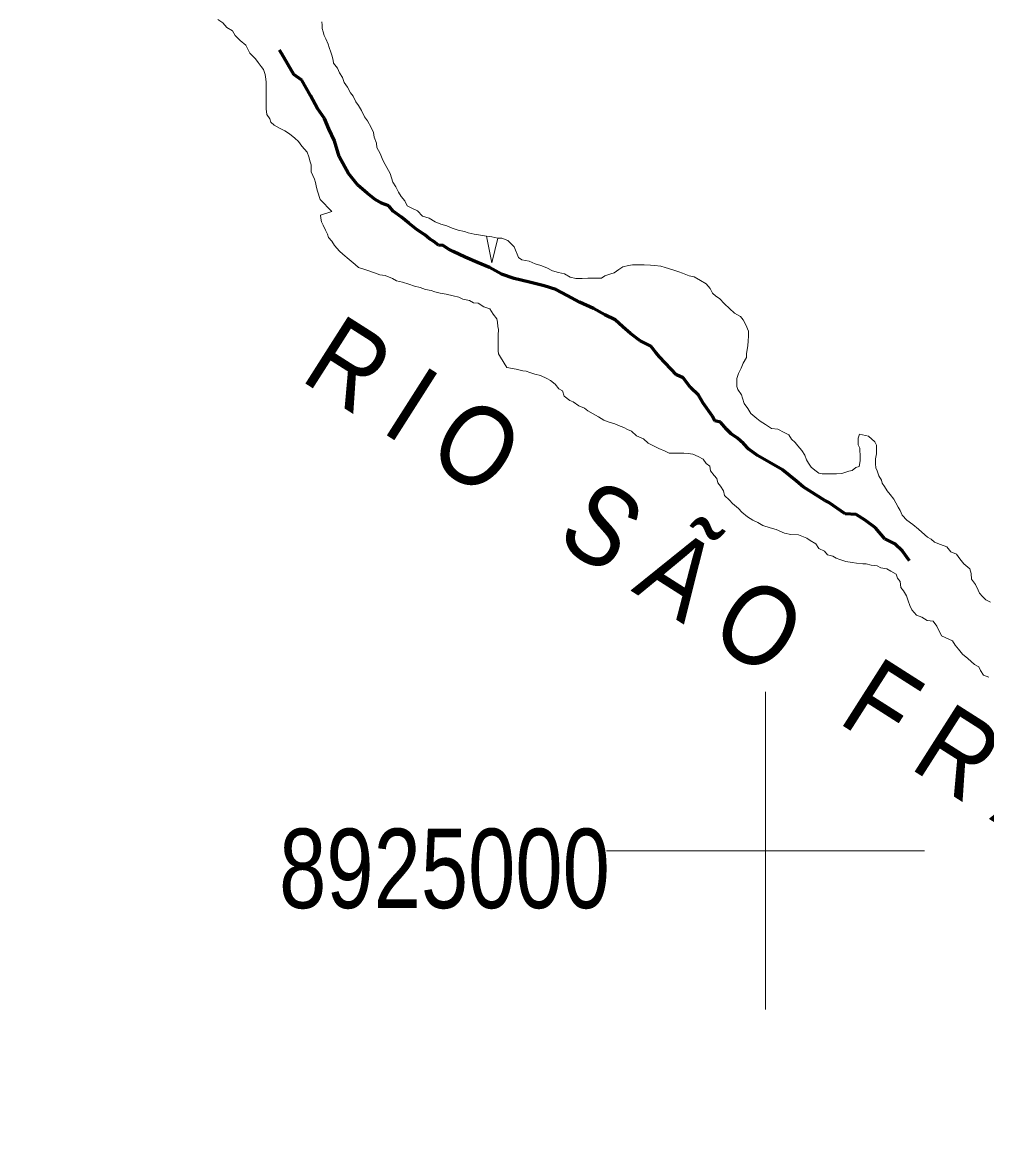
# Model space of a CAD drawing. Extents: x -1643653 to 4543381, y 1624270 to 13878484.
# Drawn here: x 645322 to 651392, y 8923156 to 8930215 of the extents above; entities that cross this region are included whole.
import ezdxf
from ezdxf.enums import TextEntityAlignment as Align

# ---------------------------------------------------------------- set-up
doc = ezdxf.new("R2010")
doc.units = 0
doc.header["$LTSCALE"] = 200
doc.linetypes.add('LONG_DASH_SHORT_DASH', pattern=[9.9, 6, -1.2, 1.5, -1.2])
for name, color, linetype, lineweight in [('2', 7, 'Continuous', 13), ('23', 7, 'Continuous', 13), ('25', 7, 'Continuous', 13), ('60', 7, 'Continuous', 13), ('7', 7, 'LONG_DASH_SHORT_DASH', 60)]:
    doc.layers.add(name, color=color, linetype=linetype, lineweight=lineweight)
for name, color, linetype in [('42', 7, 'Continuous'), ('47', 7, 'Continuous'), ('49', 7, 'Continuous')]:
    doc.layers.add(name, color=color, linetype=linetype)

msp = doc.modelspace()

# ---------------------------------------------------------------- linework, layer by layer
at = {"layer": '2'}
for p, q in [((650000, 8924000), (650000, 8926000)), ((649000, 8925000), (651000, 8925000))]:
    msp.add_line(p, q, dxfattribs=at)
at = {"layer": '23'}
for points in [[(648771.1, 8928610.7), (648733.8, 8928630.9), (648696.3, 8928641.2), (648658.9, 8928651.4), (648624, 8928669.2), (648586.6, 8928684.5), (648549.2, 8928694.7), (648511.8, 8928712.5), (648466.8, 8928720.3), (648444.5, 8928735.5), (648417.4, 8928800.8), (648377.7, 8928841.1), (648340.3, 8928856.3), (648315.3, 8928856.5), (648277.9, 8928864.3), (648242.9, 8928869.5), (648205.4, 8928874.8), (648165.5, 8928882.5), (648128, 8928890.3), (648105.5, 8928897.9), (648065.6, 8928905.7), (648028.2, 8928918.5), (647993.3, 8928933.7), (647955.8, 8928944), (647920.9, 8928959.3), (647883.6, 8928982), (647841.2, 8928994.8), (647808.9, 8929027.6), (647779, 8929042.8), (647744.1, 8929060.6), (647729.3, 8929090.7), (647707, 8929118.4), (647689.7, 8929146.1), (647672.5, 8929178.7), (647655.2, 8929208.9), (647638.1, 8929264.1), (647606, 8929319.3), (647591.2, 8929347), (647574, 8929389.7), (647554.3, 8929427.3), (647552, 8929454.9), (647537.3, 8929492.5), (647532.5, 8929522.6), (647517.8, 8929552.8), (647495.6, 8929595.5), (647475.8, 8929620.6), (647456.1, 8929660.8), (647438.8, 8929691), (647421.4, 8929713.6), (647404.2, 8929751.3), (647386.9, 8929771.4), (647369.6, 8929806.6), (647347.3, 8929836.8), (647337.6, 8929866.9), (647317.8, 8929897.1), (647305.5, 8929927.2), (647280.7, 8929957.4), (647278.4, 8929977.4), (647271.1, 8930007.5), (647263.8, 8930027.6), (647254, 8930057.7), (647246.6, 8930077.8), (647231.9, 8930110.4), (647222, 8930133), (647214.7, 8930155.6), (647209.9, 8930175.7), (647210, 8930198.2), (647207.7, 8930218.2)], [(648771.1, 8928610.7), (648733.8, 8928630.9), (648696.3, 8928641.2), (648658.9, 8928651.4), (648624, 8928669.2), (648586.6, 8928684.5), (648549.2, 8928694.7), (648511.8, 8928712.5), (648466.8, 8928720.3), (648444.5, 8928735.5), (648417.4, 8928800.8), (648377.7, 8928841.1), (648340.3, 8928856.3), (648315.3, 8928856.5), (648277.9, 8928864.3), (648242.9, 8928869.5), (648205.4, 8928874.8), (648165.5, 8928882.5), (648128, 8928890.3), (648105.5, 8928897.9), (648065.6, 8928905.7), (648028.2, 8928918.5), (647993.3, 8928933.7), (647955.8, 8928944), (647920.9, 8928959.3), (647883.6, 8928982), (647841.2, 8928994.8), (647808.9, 8929027.6), (647779, 8929042.8), (647744.1, 8929060.6), (647729.3, 8929090.7), (647707, 8929118.4), (647689.7, 8929146.1), (647672.5, 8929178.7), (647655.2, 8929208.9), (647638.1, 8929264.1), (647606, 8929319.3), (647591.2, 8929347), (647574, 8929389.7), (647554.3, 8929427.3), (647552, 8929454.9), (647537.3, 8929492.5), (647532.5, 8929522.6), (647517.8, 8929552.8), (647495.6, 8929595.5), (647475.8, 8929620.6), (647456.1, 8929660.8), (647438.8, 8929691), (647421.4, 8929713.6), (647404.2, 8929751.3), (647386.9, 8929771.4), (647369.6, 8929806.6), (647347.3, 8929836.8), (647337.6, 8929866.9), (647317.8, 8929897.1), (647305.5, 8929927.2), (647280.7, 8929957.4), (647278.4, 8929977.4), (647271.1, 8930007.5), (647263.8, 8930027.6), (647254, 8930057.7), (647246.6, 8930077.8), (647231.9, 8930110.4), (647222, 8930133), (647214.7, 8930155.6), (647209.9, 8930175.7), (647210, 8930198.2), (647207.7, 8930218.2)], [(650693.1, 8927436.3), (650693.3, 8927466.3), (650698.5, 8927498.8), (650698.7, 8927521.4), (650699, 8927553.9), (650689.1, 8927574), (650649.4, 8927609.3), (650591.9, 8927622.2), (650584.2, 8927597.2), (650584.1, 8927577.2), (650583.9, 8927554.7), (650593.8, 8927534.6), (650593.6, 8927514.6), (650596, 8927494.5), (650595.8, 8927474.5), (650595.7, 8927454.5), (650590.4, 8927419.4), (650567.8, 8927412.1), (650545.2, 8927394.7), (650525.1, 8927389.8), (650505.1, 8927382.5), (650480, 8927375.1), (650447.5, 8927372.8), (650425, 8927373), (650405, 8927373.1), (650380, 8927373.3), (650357.4, 8927373.4), (650335, 8927376.1), (650310.1, 8927396.3), (650287.7, 8927413.9), (650270.4, 8927439.1), (650258.1, 8927461.7), (650248.3, 8927489.3), (650228.5, 8927519.5), (650203.7, 8927549.7), (650186.3, 8927569.8), (650164, 8927590), (650146.7, 8927617.7), (650116.8, 8927632.9), (650076.9, 8927653.2), (650037, 8927658.4), (649999.6, 8927683.7), (649967.3, 8927704), (649944.9, 8927721.6), (649907.6, 8927751.9), (649887.9, 8927784.6), (649865.6, 8927814.8), (649855.8, 8927849.9), (649848.5, 8927870), (649826.2, 8927902.7), (649818.9, 8927922.8), (649819, 8927942.8), (649819.3, 8927972.8), (649829.5, 8928005.3), (649847.3, 8928037.7), (649860, 8928070.2), (649880.3, 8928105.1), (649880.5, 8928127.6), (649885.7, 8928155.1), (649888.3, 8928177.7), (649891.1, 8928210.2), (649893.8, 8928240.2), (649894.1, 8928270.2), (649876.8, 8928310.4), (649859.6, 8928343.1), (649842.2, 8928363.2), (649804.9, 8928383.5), (649772.6, 8928413.8), (649742.8, 8928444), (649710.5, 8928476.8), (649688.2, 8928491.9), (649665.8, 8928509.6), (649651, 8928539.7), (649626.2, 8928569.9), (649591.3, 8928590.2), (649551.5, 8928613), (649519, 8928618.2), (649476.7, 8928636), (649454.2, 8928643.7), (649416.8, 8928656.4), (649369.4, 8928671.8), (649341.9, 8928679.5), (649301.9, 8928684.7), (649277, 8928687.4), (649236.9, 8928687.7), (649201.9, 8928687.9), (649161.9, 8928688.2), (649136.9, 8928683.3), (649101.8, 8928676.1), (649076.6, 8928658.7), (649046.5, 8928638.9), (649026.4, 8928631.5), (648988.8, 8928619.2), (648968.7, 8928604.3), (648948.7, 8928604.5), (648911.2, 8928604.7), (648881.2, 8928604.9), (648846.1, 8928602.6), (648826.1, 8928602.8), (648806.1, 8928602.9), (648771.1, 8928610.7)], [(650693.1, 8927436.3), (650693.3, 8927466.3), (650698.5, 8927498.8), (650698.7, 8927521.4), (650699, 8927553.9), (650689.1, 8927574), (650649.4, 8927609.3), (650591.9, 8927622.2), (650584.2, 8927597.2), (650584.1, 8927577.2), (650583.9, 8927554.7), (650593.8, 8927534.6), (650593.6, 8927514.6), (650596, 8927494.5), (650595.8, 8927474.5), (650595.7, 8927454.5), (650590.4, 8927419.4), (650567.8, 8927412.1), (650545.2, 8927394.7), (650525.1, 8927389.8), (650505.1, 8927382.5), (650480, 8927375.1), (650447.5, 8927372.8), (650425, 8927373), (650405, 8927373.1), (650380, 8927373.3), (650357.4, 8927373.4), (650335, 8927376.1), (650310.1, 8927396.3), (650287.7, 8927413.9), (650270.4, 8927439.1), (650258.1, 8927461.7), (650248.3, 8927489.3), (650228.5, 8927519.5), (650203.7, 8927549.7), (650186.3, 8927569.8), (650164, 8927590), (650146.7, 8927617.7), (650116.8, 8927632.9), (650076.9, 8927653.2), (650037, 8927658.4), (649999.6, 8927683.7), (649967.3, 8927704), (649944.9, 8927721.6), (649907.6, 8927751.9), (649887.9, 8927784.6), (649865.6, 8927814.8), (649855.8, 8927849.9), (649848.5, 8927870), (649826.2, 8927902.7), (649818.9, 8927922.8), (649819, 8927942.8), (649819.3, 8927972.8), (649829.5, 8928005.3), (649847.3, 8928037.7), (649860, 8928070.2), (649880.3, 8928105.1), (649880.5, 8928127.6), (649885.7, 8928155.1), (649888.3, 8928177.7), (649891.1, 8928210.2), (649893.8, 8928240.2), (649894.1, 8928270.2), (649876.8, 8928310.4), (649859.6, 8928343.1), (649842.2, 8928363.2), (649804.9, 8928383.5), (649772.6, 8928413.8), (649742.8, 8928444), (649710.5, 8928476.8), (649688.2, 8928491.9), (649665.8, 8928509.6), (649651, 8928539.7), (649626.2, 8928569.9), (649591.3, 8928590.2), (649551.5, 8928613), (649519, 8928618.2), (649476.7, 8928636), (649454.2, 8928643.7), (649416.8, 8928656.4), (649369.4, 8928671.8), (649341.9, 8928679.5), (649301.9, 8928684.7), (649277, 8928687.4), (649236.9, 8928687.7), (649201.9, 8928687.9), (649161.9, 8928688.2), (649136.9, 8928683.3), (649101.8, 8928676.1), (649076.6, 8928658.7), (649046.5, 8928638.9), (649026.4, 8928631.5), (648988.8, 8928619.2), (648968.7, 8928604.3), (648948.7, 8928604.5), (648911.2, 8928604.7), (648881.2, 8928604.9), (648846.1, 8928602.6), (648826.1, 8928602.8), (648806.1, 8928602.9), (648771.1, 8928610.7)], [(651416.8, 8926565.3), (651386.9, 8926580.5), (651367, 8926600.7), (651347.2, 8926620.8), (651339.8, 8926640.9), (651322.6, 8926676.1), (651297.8, 8926708.8), (651295.6, 8926746.3), (651285.8, 8926773.9), (651248.5, 8926806.7), (651223.7, 8926836.9), (651201.5, 8926867.1), (651166.6, 8926882.4), (651141.8, 8926912.6), (651101.9, 8926927.9), (651064.5, 8926943.1), (651042.1, 8926960.8), (651019.7, 8926973.5), (650984.9, 8927006.3), (650962.5, 8927023.9), (650927.8, 8927054.2), (650890.5, 8927082), (650860.7, 8927112.2), (650848.4, 8927142.3), (650836, 8927162.5), (650821.2, 8927190.1), (650808.9, 8927212.7), (650784.1, 8927242.9), (650766.8, 8927265.6), (650749.5, 8927293.2), (650734.6, 8927313.3), (650729.8, 8927333.4), (650712.5, 8927361.1), (650702.7, 8927391.2), (650695.4, 8927411.2), (650693.1, 8927436.3)], [(651416.8, 8926565.3), (651386.9, 8926580.5), (651367, 8926600.7), (651347.2, 8926620.8), (651339.8, 8926640.9), (651322.6, 8926676.1), (651297.8, 8926708.8), (651295.6, 8926746.3), (651285.8, 8926773.9), (651248.5, 8926806.7), (651223.7, 8926836.9), (651201.5, 8926867.1), (651166.6, 8926882.4), (651141.8, 8926912.6), (651101.9, 8926927.9), (651064.5, 8926943.1), (651042.1, 8926960.8), (651019.7, 8926973.5), (650984.9, 8927006.3), (650962.5, 8927023.9), (650927.8, 8927054.2), (650890.5, 8927082), (650860.7, 8927112.2), (650848.4, 8927142.3), (650836, 8927162.5), (650821.2, 8927190.1), (650808.9, 8927212.7), (650784.1, 8927242.9), (650766.8, 8927265.6), (650749.5, 8927293.2), (650734.6, 8927313.3), (650729.8, 8927333.4), (650712.5, 8927361.1), (650702.7, 8927391.2), (650695.4, 8927411.2), (650693.1, 8927436.3)]]:
    msp.add_lwpolyline(points, dxfattribs=at)
at = {"layer": '25'}
for points in [[(647140.8, 8929317.4), (647133.5, 8929337.5), (647126.2, 8929367.6), (647113.9, 8929397.7), (647081.7, 8929435.5), (647059.4, 8929465.7), (647037, 8929485.8), (647004.7, 8929513.6), (646974.9, 8929531.3), (646940, 8929549.1), (646907.6, 8929566.8), (646885.2, 8929587), (646880.4, 8929607.1), (646860.6, 8929634.7), (646855.9, 8929669.8), (646856, 8929689.8), (646856.3, 8929729.9), (646856.6, 8929772.4), (646856.9, 8929810), (646857.1, 8929837.5), (646854.8, 8929857.6), (646850, 8929887.6), (646840.2, 8929917.8), (646825.4, 8929937.9), (646805.6, 8929963), (646790.7, 8929985.7), (646753.5, 8930021), (646728.8, 8930071.2), (646694.1, 8930101.5), (646661.8, 8930131.7), (646644.5, 8930161.9), (646609.6, 8930182.1), (646584.9, 8930212.3), (646552.5, 8930232.6)], [(647207.7, 8930218.2), (647210, 8930198.2), (647209.9, 8930175.7), (647214.7, 8930155.6), (647222, 8930133), (647231.9, 8930110.4), (647246.6, 8930077.8), (647254, 8930057.7), (647263.8, 8930027.6), (647271.1, 8930007.5), (647278.4, 8929977.4), (647280.7, 8929957.4), (647305.5, 8929927.2), (647317.8, 8929897.1), (647337.6, 8929866.9), (647347.3, 8929836.8), (647369.6, 8929806.6), (647386.9, 8929771.4), (647404.2, 8929751.3), (647421.4, 8929713.6), (647438.8, 8929691), (647456.1, 8929660.8), (647475.8, 8929620.6), (647495.6, 8929595.5), (647517.8, 8929552.8), (647532.5, 8929522.6), (647537.3, 8929492.5), (647552, 8929454.9), (647554.3, 8929427.3), (647574, 8929389.7), (647591.2, 8929347), (647606, 8929319.3), (647638.1, 8929264.1), (647655.2, 8929208.9), (647672.5, 8929178.7), (647689.7, 8929146.1), (647707, 8929118.4), (647729.3, 8929090.7), (647744.1, 8929060.6), (647779, 8929042.8), (647808.9, 8929027.6), (647841.2, 8928994.8), (647883.6, 8928982), (647920.9, 8928959.3), (647955.8, 8928944), (647993.3, 8928933.7), (648028.2, 8928918.5), (648065.6, 8928905.7), (648105.5, 8928897.9), (648128, 8928890.3), (648165.5, 8928882.5), (648205.4, 8928874.8), (648242.9, 8928869.5), (648277.9, 8928700.4), (648315.3, 8928856.5), (648340.3, 8928856.3), (648377.7, 8928841.1), (648417.4, 8928800.8), (648444.5, 8928735.5), (648466.8, 8928720.3), (648511.8, 8928712.5), (648549.2, 8928694.7), (648586.6, 8928684.5), (648624, 8928669.2), (648658.9, 8928651.4), (648696.3, 8928641.2), (648733.8, 8928630.9), (648771.1, 8928610.7)], [(649677.1, 8927362.9), (649654.8, 8927390.6), (649650, 8927420.7), (649627.6, 8927438.3), (649607.8, 8927466), (649575.4, 8927481.2), (649543, 8927496.5), (649513, 8927501.7), (649485.5, 8927501.9), (649445.5, 8927502.1), (649423, 8927502.3), (649393, 8927502.5), (649368.1, 8927515.2), (649328.2, 8927532.9), (649295.8, 8927548.2), (649260.9, 8927565.9), (649231.1, 8927593.7), (649188.7, 8927611.5), (649156.5, 8927641.7), (649131.5, 8927651.9), (649109.1, 8927664.6), (649074.2, 8927677.3), (649051.8, 8927687.5), (649016.8, 8927697.7), (648981.9, 8927710.5), (648949.5, 8927730.7), (648914.7, 8927751), (648882.3, 8927768.7), (648859.9, 8927786.4), (648825, 8927801.7), (648790.2, 8927826.9), (648767.7, 8927834.6), (648732.9, 8927862.3), (648723.2, 8927895), (648698.3, 8927907.6), (648676, 8927937.8), (648646.2, 8927960.6), (648623.7, 8927973.2), (648583.8, 8927991), (648548.9, 8928001.2), (648516.5, 8928011.5), (648494, 8928019.1), (648471.5, 8928021.8), (648431.6, 8928032.1), (648371.7, 8928042.5), (648332.1, 8928107.8), (648319.8, 8928127.9), (648317.4, 8928148), (648317.7, 8928183), (648317.9, 8928210.6), (648318.2, 8928245.6), (648318.4, 8928280.7), (648316.1, 8928300.7), (648313.8, 8928328.3), (648309, 8928348.3), (648286.7, 8928378.5), (648264.4, 8928411.2), (648227, 8928424), (648192.1, 8928446.7), (648162.2, 8928449.4), (648137.3, 8928464.6), (648094.8, 8928472.4), (648069.9, 8928485.1), (648034.9, 8928492.8), (647990, 8928503.2), (647952.5, 8928510.9), (647917.6, 8928518.7), (647895.1, 8928526.3), (647860.2, 8928534.1), (647825.2, 8928546.8), (647790.3, 8928554.6), (647755.4, 8928567.3), (647715.5, 8928580.1), (647678, 8928587.8), (647653.1, 8928603), (647605.7, 8928620.9), (647573.2, 8928626.1), (647538.3, 8928638.8), (647483.4, 8928656.7), (647438.5, 8928672), (647416.2, 8928689.7), (647378.9, 8928722.5), (647339.1, 8928755.3), (647319.3, 8928775.5), (647287, 8928810.7), (647269.7, 8928838.4), (647249.9, 8928861.1), (647242.5, 8928881.1), (647230.2, 8928906.2), (647215.5, 8928938.9), (647205.6, 8928959), (647200.8, 8928981.6), (647198.4, 8929001.6), (647271.1, 8929023.6), (647196.7, 8929099.2), (647179.6, 8929151.9), (647174.7, 8929174.5), (647167.5, 8929207.1), (647160.1, 8929227.2), (647140.5, 8929274.8), (647140.8, 8929317.4)], [(648771.1, 8928610.7), (648806.1, 8928602.9), (648826.1, 8928602.8), (648846.1, 8928602.6), (648881.2, 8928604.9), (648911.2, 8928604.7), (648948.7, 8928604.5), (648968.7, 8928604.3), (648988.8, 8928619.2), (649026.4, 8928631.5), (649046.5, 8928638.9), (649076.6, 8928658.7), (649101.8, 8928676.1), (649136.9, 8928683.3), (649161.9, 8928688.2), (649201.9, 8928687.9), (649236.9, 8928687.7), (649277, 8928687.4), (649301.9, 8928684.7), (649341.9, 8928679.5), (649369.4, 8928671.8), (649416.8, 8928656.4), (649454.2, 8928643.7), (649476.7, 8928636), (649519, 8928618.2), (649551.5, 8928613), (649591.3, 8928590.2), (649626.2, 8928569.9), (649651, 8928539.7), (649665.8, 8928509.6), (649688.2, 8928491.9), (649710.5, 8928476.8), (649742.8, 8928444), (649772.6, 8928413.8), (649804.9, 8928383.5), (649842.2, 8928363.2), (649859.6, 8928343.1), (649876.8, 8928310.4), (649894.1, 8928270.2), (649893.8, 8928240.2), (649891.1, 8928210.2), (649888.3, 8928177.7), (649885.7, 8928155.1), (649880.5, 8928127.6), (649880.3, 8928105.1), (649860, 8928070.2), (649847.3, 8928037.7), (649829.5, 8928005.3), (649819.3, 8927972.8), (649819, 8927942.8), (649818.9, 8927922.8), (649826.2, 8927902.7), (649848.5, 8927870), (649855.8, 8927849.9), (649865.6, 8927814.8), (649887.9, 8927784.6), (649907.6, 8927751.9), (649944.9, 8927721.6), (649967.3, 8927704), (649999.6, 8927683.7), (650037, 8927658.4), (650076.9, 8927653.2), (650116.8, 8927632.9), (650146.7, 8927617.7), (650164, 8927590), (650186.3, 8927569.8), (650203.7, 8927549.7), (650228.5, 8927519.5), (650248.3, 8927489.3), (650258.1, 8927461.7), (650270.4, 8927439.1), (650287.7, 8927413.9), (650310.1, 8927396.3), (650335, 8927376.1), (650357.4, 8927373.4), (650380, 8927373.3), (650405, 8927373.1), (650425, 8927373), (650447.5, 8927372.8), (650480, 8927375.1), (650505.1, 8927382.5), (650525.1, 8927389.8), (650545.2, 8927394.7), (650567.8, 8927412.1), (650590.4, 8927419.4), (650595.7, 8927454.5), (650595.8, 8927474.5), (650596, 8927494.5), (650593.6, 8927514.6), (650593.8, 8927534.6), (650583.9, 8927554.7), (650584.1, 8927577.2), (650584.2, 8927597.2), (650591.9, 8927622.2), (650649.4, 8927609.3), (650689.1, 8927574), (650699, 8927553.9), (650698.7, 8927521.4), (650698.5, 8927498.8), (650693.3, 8927466.3), (650693.1, 8927436.3)], [(650693.1, 8927436.3), (650695.4, 8927411.2), (650702.7, 8927391.2), (650712.5, 8927361.1), (650729.8, 8927333.4), (650734.6, 8927313.3), (650749.5, 8927293.2), (650766.8, 8927265.6), (650784.1, 8927242.9), (650808.9, 8927212.7), (650821.2, 8927190.1), (650836, 8927162.5), (650848.4, 8927142.3), (650860.7, 8927112.2), (650890.5, 8927082), (650927.8, 8927054.2), (650962.5, 8927023.9), (650984.9, 8927006.3), (651019.7, 8926973.5), (651042.1, 8926960.8), (651064.5, 8926943.1), (651101.9, 8926927.9), (651141.8, 8926912.6), (651166.6, 8926882.4), (651201.5, 8926867.1), (651223.7, 8926836.9), (651248.5, 8926806.7), (651285.8, 8926773.9), (651295.6, 8926746.3), (651297.8, 8926708.8), (651322.6, 8926676.1), (651339.8, 8926640.9), (651347.2, 8926620.8), (651367, 8926600.7), (651386.9, 8926580.5), (651416.8, 8926565.3)], [(651405.7, 8926092.2), (651373.2, 8926104.9), (651353.5, 8926135.1), (651343.6, 8926157.7), (651316.2, 8926172.9), (651293.8, 8926190.6), (651274, 8926210.7), (651239.2, 8926238.5), (651214.4, 8926268.7), (651194.6, 8926293.9), (651177.3, 8926321.5), (651107.5, 8926352), (651078, 8926414.8), (651055.7, 8926445), (651018.2, 8926450.2), (650983.3, 8926470.5), (650950.9, 8926483.2), (650921.2, 8926516), (650908.9, 8926543.6), (650899.1, 8926573.7), (650886.8, 8926603.8), (650869.6, 8926636.5), (650852.2, 8926656.6), (650847.5, 8926694.2), (650830.2, 8926716.9), (650822.8, 8926742), (650788, 8926759.7), (650763.1, 8926774.9), (650725.6, 8926780.2), (650703.2, 8926792.8), (650665.7, 8926798.1), (650633.2, 8926805.8), (650613.2, 8926805.9), (650573.2, 8926811.2), (650545.8, 8926813.9), (650505.8, 8926821.7), (650468.4, 8926834.4), (650445.9, 8926842.1), (650423.5, 8926854.8), (650391.1, 8926862.5), (650371.2, 8926885.1), (650336.3, 8926902.9), (650316.6, 8926933.1), (650281.7, 8926953.3), (650259.3, 8926968.5), (650229.4, 8926981.2), (650207, 8926988.9), (650159.5, 8926991.7), (650119.5, 8926999.5), (650067.1, 8927022.3), (650029.7, 8927032.6), (649982.3, 8927047.9), (649952.4, 8927065.7), (649920, 8927080.9), (649887.7, 8927101.1), (649850.4, 8927131.4), (649830.5, 8927154.1), (649793.3, 8927186.9), (649773.4, 8927207.1), (649741.1, 8927237.3), (649736.3, 8927264.9), (649716.6, 8927295.1), (649699.2, 8927315.2), (649694.4, 8927342.8), (649677.1, 8927362.9)]]:
    msp.add_lwpolyline(points, dxfattribs=at)
at = {"layer": '60', "lineweight": 25}
msp.add_spline([(814781, 9009175.5), (814787.2, 9009173.4), (814796.9, 9009173.4), (814799.4, 9009172.4), (814805.1, 9009174.5), (814805.6, 9009176.5), (814811.7, 9009179.5), (814811.7, 9009179.5), (814801.5, 9009181), (814790.7, 9009181.5), (814784.1, 9009183.1), (814777.4, 9009185.1), (814778.4, 9009175.5)], degree=3, dxfattribs=at)
at = {"layer": '7'}
for points in [[(647971.9, 8928809.9), (647942, 8928812.6), (647912.1, 8928835.3), (647884.7, 8928852.9), (647854.9, 8928878.1), (647807.6, 8928908.4), (647755.4, 8928951.2), (647708.1, 8928989), (647655.9, 8929026.8), (647628.6, 8929059.5), (647583.7, 8929077.2), (647543.9, 8929100), (647491.7, 8929140.3), (647434.5, 8929190.6), (647375, 8929263.5), (647315.7, 8929371.4), (647286.4, 8929469.2), (647251.9, 8929544.4), (647224.8, 8929609.6), (647180.2, 8929672.4), (647135.8, 8929755.2), (647081.4, 8929850.6), (647031.7, 8929885.9), (646955.1, 8930016.4), (646941, 8930039.5)], [(650905.5, 8926825.8), (650861.5, 8926885.3), (650814.4, 8926933.1), (650752.1, 8926963.5), (650692.5, 8927033.8), (650627.8, 8927081.7), (650570.6, 8927117.1), (650500.6, 8927119.9), (650398.6, 8927193.1), (650373.7, 8927205.7), (650236.8, 8927291.5), (650194.5, 8927326.8), (650107.5, 8927397.3), (650022.8, 8927445.3), (649950.6, 8927488.2), (649895.8, 8927528.5), (649861.1, 8927563.7), (649823.8, 8927596.5), (649784, 8927624.2), (649754.2, 8927654.4), (649717, 8927697.1), (649682.1, 8927707.3), (649664.8, 8927737.4), (649607.8, 8927817.8), (649578.1, 8927868), (649528.5, 8927915.8), (649481.4, 8927976.1), (649439, 8927996.4), (649332.2, 8928109.6), (649309.9, 8928137.2), (649277.7, 8928177.4), (649210.4, 8928210.3), (649150.7, 8928255.7), (649101, 8928298.5), (649053.8, 8928341.2), (648989, 8928374.1), (648916.8, 8928414.6), (648829.6, 8928452.5), (648752.3, 8928495.5), (648680.1, 8928533.4), (648607.8, 8928556.3), (648515.4, 8928579.3), (648418.1, 8928602.4), (648338.2, 8928630.3), (648263.5, 8928670.7), (648186.2, 8928703.7), (648109, 8928736.6), (648034.2, 8928772.1), (648004.3, 8928787.2), (647971.9, 8928809.9)]]:
    msp.add_lwpolyline(points, dxfattribs=at)

# ---------------------------------------------------------------- texts
at = {"layer": '42'}
msp.add_text('S  E  R  G  I  P  E', height=2000, rotation=329.237, dxfattribs=at).set_placement((637761.3, 8923891.3))
at = {"layer": '47', "width": 0.8}
msp.add_text('8925000', height=500, dxfattribs=at).set_placement((647979.3, 8924638.8), align=Align.CENTER)
at = {"layer": '49', "width": 0.9}
msp.add_text('R I O   S Ã O   F R A N C I S C O', height=500, rotation=327.505, dxfattribs=at).set_placement((647062, 8927967.9))

doc.saveas('drawing.dxf')
